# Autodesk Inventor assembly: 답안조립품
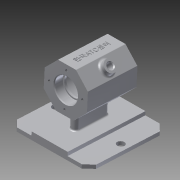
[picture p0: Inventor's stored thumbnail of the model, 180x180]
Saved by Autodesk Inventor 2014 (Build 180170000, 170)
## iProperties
Created: 2018-06
Part Number: 답안조립품
Document SubType Name: Assembly
Designer: kh
Author: kh
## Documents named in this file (2)
- C:\Users\kh\Desktop\480607V1008\답안조립품.iam
- C:\Users\kh\Desktop\480607V1008\답안본체.ipt
